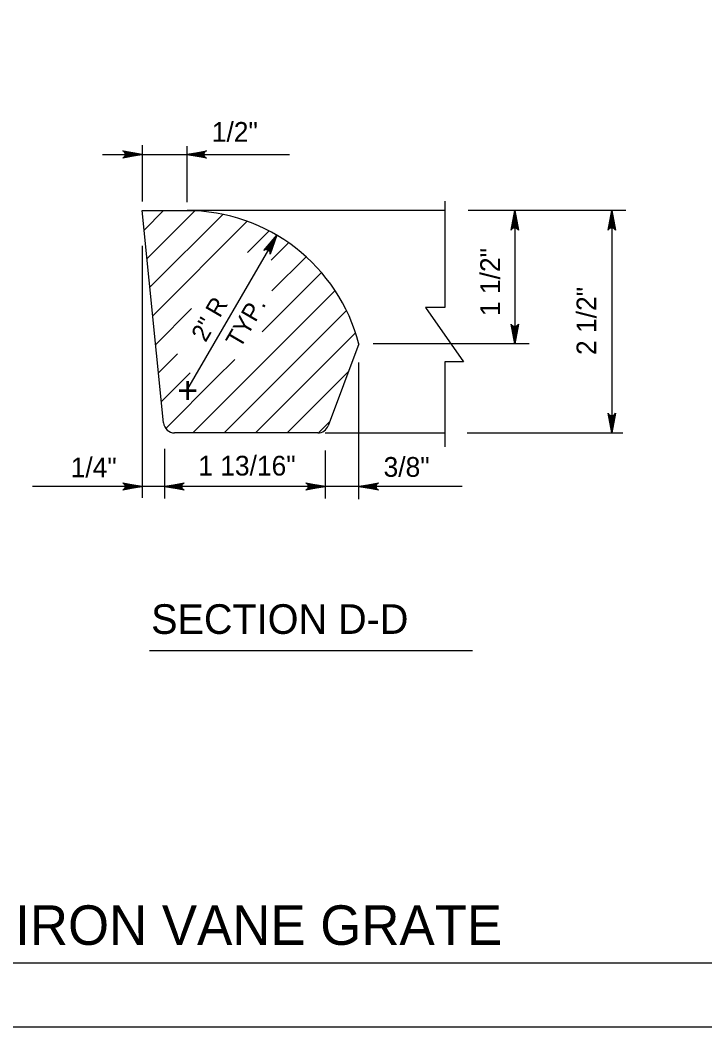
# Model space of a CAD drawing. Extents: x 2087776 to 2104538, y 970919 to 982612.
# Drawn here: x 2096713 to 2097054, y 976815 to 977317 of the extents above; entities that cross this region are included whole.
import ezdxf

# ---------------------------------------------------------------- set-up
doc = ezdxf.new("R2010")
doc.units = 0
doc.layers.add('1', color=7, linetype='Continuous')

msp = doc.modelspace()

# ---------------------------------------------------------------- linework, layer by layer
at = {"layer": '1'}
for p, q in [((2096773.77, 977254.28), (2096773.77, 977226.16)), ((2096795.92, 977253.76), (2096795.92, 977225.88)), ((2096753.92, 977249.72), (2096847.23, 977249.72)), ((2096924.63, 977226.43), (2096924.63, 977173.43)), ((2096784.34, 977115.93), (2096773.77, 977221.68)), ((2096773.77, 977221.68), (2096796.17, 977221.68)), ((2096924.63, 977221.68), (2096796.17, 977221.68)), ((2097014.91, 977221.68), (2096936.25, 977221.68)), ((2096959.46, 977221.68), (2096959.46, 977155.37)), ((2097007.85, 977221.68), (2097007.85, 977110.95)), ((2096840.9, 977209.43), (2096795.86, 977132.05)), ((2096773.77, 977204.17), (2096773.77, 977078.64)), ((2096924.63, 977173.43), (2096914.98, 977173.43)), ((2096914.98, 977173.43), (2096934, 977146.35)), ((2096881.73, 977155.37), (2096866.47, 977114.54)), ((2096966.68, 977155.37), (2096888.93, 977155.37)), ((2096881.73, 977077.85), (2096881.73, 977146.01)), ((2096934, 977146.35), (2096924.63, 977146.35)), ((2096924.63, 977146.35), (2096924.63, 977104.04)), ((2096795.86, 977132.05), (2096795.86, 977132.05)), ((2096861.28, 977110.95), (2096789.86, 977110.95)), ((2096864.95, 977110.95), (2096924.63, 977110.95)), ((2096935.77, 977110.95), (2097013.38, 977110.95)), ((2096784.84, 977103), (2096784.84, 977078.25)), ((2096865.13, 977078.25), (2096865.13, 977102.11)), ((2096933.35, 977084.24), (2096718.94, 977084.24)), ((2096777.42, 977002.5), (2096938.49, 977002.5)), ((2096478.9, 976846.96), (2097073.31, 976846.96))]:
    msp.add_line(p, q, dxfattribs=at)
for points in [[(2098759.93, 976815.01), (2098759.93, 978665.4), (2096181.19, 978665.4), (2096181.19, 976815.01), (2098759.93, 976815.01), (2098759.93, 976901.49), (2098103.76, 976901.49), (2098103.76, 977113.68), (2098759.93, 977113.68), (2098759.93, 977208.71), (2098103.76, 977208.71), (2098103.76, 976815.01), (2098362.29, 976815.01), (2098362.29, 976901.49), (2098362.29, 976815.01), (2098614.92, 976815.01), (2098614.92, 976901.49), (2098614.92, 976861.08), (2098759.93, 976861.08)], [(2096773.77, 977249.72), (2096763.99, 977247.88), (2096764.37, 977248.15), (2096764.74, 977248.41), (2096764.94, 977248.73), (2096765.13, 977249.06), (2096765.19, 977249.39), (2096765.24, 977249.72), (2096765.19, 977250.05), (2096765.13, 977250.37), (2096764.94, 977250.7), (2096764.74, 977251.03), (2096764.37, 977251.29), (2096763.99, 977251.55), (2096773.77, 977249.72), (2096764.37, 977251.29), (2096764.74, 977251.03), (2096773.77, 977249.72), (2096764.94, 977250.7), (2096765.13, 977250.37), (2096773.77, 977249.72), (2096765.19, 977250.05), (2096765.24, 977249.72), (2096773.77, 977249.72), (2096765.19, 977249.39), (2096765.13, 977249.06), (2096773.77, 977249.72), (2096764.94, 977248.73), (2096764.74, 977248.41), (2096773.77, 977249.72), (2096764.37, 977248.15)], [(2096795.92, 977249.72), (2096805.7, 977251.55), (2096805.33, 977251.29), (2096804.95, 977251.03), (2096804.76, 977250.7), (2096804.56, 977250.37), (2096804.51, 977250.05), (2096804.45, 977249.72), (2096804.51, 977249.39), (2096804.56, 977249.06), (2096804.76, 977248.73), (2096804.95, 977248.41), (2096805.33, 977248.15), (2096805.7, 977247.88), (2096795.92, 977249.72), (2096805.33, 977248.15), (2096804.95, 977248.41), (2096795.92, 977249.72), (2096804.76, 977248.73), (2096804.56, 977249.06), (2096795.92, 977249.72), (2096804.51, 977249.39), (2096804.45, 977249.72), (2096795.92, 977249.72), (2096804.51, 977250.05), (2096804.56, 977250.37), (2096795.92, 977249.72), (2096804.76, 977250.7), (2096804.95, 977251.03), (2096795.92, 977249.72), (2096805.33, 977251.29)], [(2096774.74, 977212.02), (2096784.4, 977221.68)], [(2096776.16, 977197.78), (2096799.96, 977221.58)], [(2096959.46, 977221.68), (2096961.3, 977211.9), (2096961.04, 977212.27), (2096960.78, 977212.65), (2096960.45, 977212.84), (2096960.12, 977213.04), (2096959.79, 977213.09), (2096959.46, 977213.15), (2096959.13, 977213.09), (2096958.81, 977213.04), (2096958.48, 977212.84), (2096958.15, 977212.65), (2096957.89, 977212.27), (2096957.63, 977211.9), (2096959.46, 977221.68), (2096957.89, 977212.27), (2096958.15, 977212.65), (2096959.46, 977221.68), (2096958.48, 977212.84), (2096958.81, 977213.04), (2096959.46, 977221.68), (2096959.13, 977213.09), (2096959.46, 977213.15), (2096959.46, 977221.68), (2096959.79, 977213.09), (2096960.12, 977213.04), (2096959.46, 977221.68), (2096960.45, 977212.84), (2096960.78, 977212.65), (2096959.46, 977221.68), (2096961.04, 977212.27)], [(2097007.85, 977221.68), (2097009.68, 977211.9), (2097009.42, 977212.27), (2097009.16, 977212.65), (2097008.83, 977212.84), (2097008.5, 977213.04), (2097008.18, 977213.09), (2097007.85, 977213.15), (2097007.52, 977213.09), (2097007.19, 977213.04), (2097006.86, 977212.84), (2097006.54, 977212.65), (2097006.28, 977212.27), (2097006.01, 977211.9), (2097007.85, 977221.68), (2097006.28, 977212.27), (2097006.54, 977212.65), (2097007.85, 977221.68), (2097006.86, 977212.84), (2097007.19, 977213.04), (2097007.85, 977221.68), (2097007.52, 977213.09), (2097007.85, 977213.15), (2097007.85, 977221.68), (2097008.18, 977213.09), (2097008.5, 977213.04), (2097007.85, 977221.68), (2097008.83, 977212.84), (2097009.16, 977212.65), (2097007.85, 977221.68), (2097009.42, 977212.27)], [(2096777.59, 977183.55), (2096813.88, 977219.84)], [(2096779.01, 977169.31), (2096826.09, 977216.39)], [(2096826.26, 977200.89), (2096836.97, 977211.6)], [(2096840.9, 977209.43), (2096837.56, 977200.05), (2096837.53, 977200.51), (2096837.49, 977200.97), (2096837.3, 977201.3), (2096837.12, 977201.63), (2096836.86, 977201.85), (2096836.61, 977202.06), (2096836.3, 977202.18), (2096835.98, 977202.29), (2096835.6, 977202.29), (2096835.22, 977202.29), (2096834.81, 977202.09), (2096834.39, 977201.9), (2096840.9, 977209.43), (2096834.81, 977202.09), (2096835.22, 977202.29), (2096840.9, 977209.43), (2096835.6, 977202.29), (2096835.98, 977202.29), (2096840.9, 977209.43), (2096836.3, 977202.18), (2096836.61, 977202.06), (2096840.9, 977209.43), (2096836.86, 977201.85), (2096837.12, 977201.63), (2096840.9, 977209.43), (2096837.3, 977201.3), (2096837.49, 977200.97), (2096840.9, 977209.43), (2096837.53, 977200.51)], [(2096837.95, 977196.93), (2096846.71, 977205.7)], [(2096838.4, 977181.72), (2096855.43, 977198.74)], [(2096833.58, 977161.23), (2096863.16, 977190.81)], [(2096856.84, 977168.85), (2096869.88, 977181.89)], [(2096780.43, 977155.07), (2096798.35, 977172.99)], [(2096814.61, 977110.95), (2096875.58, 977171.92)], [(2096815.47, 977127.48), (2096857.26, 977169.27)], [(2096959.46, 977155.37), (2096957.63, 977165.16), (2096957.89, 977164.78), (2096958.15, 977164.41), (2096958.48, 977164.21), (2096958.81, 977164.02), (2096959.13, 977163.96), (2096959.46, 977163.91), (2096959.79, 977163.96), (2096960.12, 977164.02), (2096960.45, 977164.21), (2096960.78, 977164.41), (2096961.04, 977164.78), (2096961.3, 977165.16), (2096959.46, 977155.37), (2096961.04, 977164.78), (2096960.78, 977164.41), (2096959.46, 977155.37), (2096960.45, 977164.21), (2096960.12, 977164.02), (2096959.46, 977155.37), (2096959.79, 977163.96), (2096959.46, 977163.91), (2096959.46, 977155.37), (2096959.13, 977163.96), (2096958.81, 977164.02), (2096959.46, 977155.37), (2096958.48, 977164.21), (2096958.15, 977164.41), (2096959.46, 977155.37), (2096957.89, 977164.78)], [(2096830.27, 977110.95), (2096880.11, 977160.79)], [(2096781.86, 977140.83), (2096791.3, 977150.28)], [(2096810.16, 977137.81), (2096819.86, 977147.51)], [(2096783.28, 977126.6), (2096797.55, 977140.87)], [(2096845.92, 977110.95), (2096876.59, 977141.61)], [(2096785.46, 977113.11), (2096810.98, 977138.64)], [(2096798.94, 977110.95), (2096815.36, 977127.36)], [(2097007.85, 977110.95), (2097006.01, 977120.73), (2097006.28, 977120.35), (2097006.54, 977119.98), (2097006.86, 977119.78), (2097007.19, 977119.59), (2097007.52, 977119.53), (2097007.85, 977119.48), (2097008.18, 977119.53), (2097008.5, 977119.59), (2097008.83, 977119.78), (2097009.16, 977119.98), (2097009.42, 977120.35), (2097009.68, 977120.73), (2097007.85, 977110.95), (2097009.42, 977120.35), (2097009.16, 977119.98), (2097007.85, 977110.95), (2097008.83, 977119.78), (2097008.5, 977119.59), (2097007.85, 977110.95), (2097008.18, 977119.53), (2097007.85, 977119.48), (2097007.85, 977110.95), (2097007.52, 977119.53), (2097007.19, 977119.59), (2097007.85, 977110.95), (2097006.86, 977119.78), (2097006.54, 977119.98), (2097007.85, 977110.95), (2097006.28, 977120.35)], [(2096861.6, 977110.96), (2096867.24, 977116.6)], [(2096773.77, 977084.24), (2096763.99, 977082.41), (2096764.37, 977082.67), (2096764.74, 977082.93), (2096764.94, 977083.26), (2096765.13, 977083.58), (2096765.19, 977083.91), (2096765.24, 977084.24), (2096765.19, 977084.57), (2096765.13, 977084.9), (2096764.94, 977085.22), (2096764.74, 977085.55), (2096764.37, 977085.81), (2096763.99, 977086.07), (2096773.77, 977084.24), (2096764.37, 977085.81), (2096764.74, 977085.55), (2096773.77, 977084.24), (2096764.94, 977085.22), (2096765.13, 977084.9), (2096773.77, 977084.24), (2096765.19, 977084.57), (2096765.24, 977084.24), (2096773.77, 977084.24), (2096765.19, 977083.91), (2096765.13, 977083.58), (2096773.77, 977084.24), (2096764.94, 977083.26), (2096764.74, 977082.93), (2096773.77, 977084.24), (2096764.37, 977082.67)], [(2096784.84, 977084.24), (2096794.63, 977086.07), (2096794.25, 977085.81), (2096793.87, 977085.55), (2096793.68, 977085.22), (2096793.49, 977084.9), (2096793.43, 977084.57), (2096793.37, 977084.24), (2096793.43, 977083.91), (2096793.49, 977083.58), (2096793.68, 977083.26), (2096793.87, 977082.93), (2096794.25, 977082.67), (2096794.63, 977082.41), (2096784.84, 977084.24), (2096794.25, 977082.67), (2096793.87, 977082.93), (2096784.84, 977084.24), (2096793.68, 977083.26), (2096793.49, 977083.58), (2096784.84, 977084.24), (2096793.43, 977083.91), (2096793.37, 977084.24), (2096784.84, 977084.24), (2096793.43, 977084.57), (2096793.49, 977084.9), (2096784.84, 977084.24), (2096793.68, 977085.22), (2096793.87, 977085.55), (2096784.84, 977084.24), (2096794.25, 977085.81)], [(2096865.13, 977084.24), (2096855.34, 977082.41), (2096855.72, 977082.67), (2096856.09, 977082.93), (2096856.29, 977083.26), (2096856.48, 977083.58), (2096856.54, 977083.91), (2096856.6, 977084.24), (2096856.54, 977084.57), (2096856.48, 977084.9), (2096856.29, 977085.22), (2096856.09, 977085.55), (2096855.72, 977085.81), (2096855.34, 977086.07), (2096865.13, 977084.24), (2096855.72, 977085.81), (2096856.09, 977085.55), (2096865.13, 977084.24), (2096856.29, 977085.22), (2096856.48, 977084.9), (2096865.13, 977084.24), (2096856.54, 977084.57), (2096856.6, 977084.24), (2096865.13, 977084.24), (2096856.54, 977083.91), (2096856.48, 977083.58), (2096865.13, 977084.24), (2096856.29, 977083.26), (2096856.09, 977082.93), (2096865.13, 977084.24), (2096855.72, 977082.67)], [(2096881.73, 977084.24), (2096891.52, 977086.07), (2096891.14, 977085.81), (2096890.76, 977085.55), (2096890.57, 977085.22), (2096890.38, 977084.9), (2096890.32, 977084.57), (2096890.26, 977084.24), (2096890.32, 977083.91), (2096890.38, 977083.58), (2096890.57, 977083.26), (2096890.76, 977082.93), (2096891.14, 977082.67), (2096891.52, 977082.41), (2096881.73, 977084.24), (2096891.14, 977082.67), (2096890.76, 977082.93), (2096881.73, 977084.24), (2096890.57, 977083.26), (2096890.38, 977083.58), (2096881.73, 977084.24), (2096890.32, 977083.91), (2096890.26, 977084.24), (2096881.73, 977084.24), (2096890.32, 977084.57), (2096890.38, 977084.9), (2096881.73, 977084.24), (2096890.57, 977085.22), (2096890.76, 977085.55), (2096881.73, 977084.24), (2096891.14, 977085.81)]]:
    msp.add_lwpolyline(points, dxfattribs=at)
for centre, radius, start, end in [((2096795.97, 977133.09), 88.58, 14.3767, 90.1346), ((2096789.86, 977116.48), 5.54, 185.7106, 270), ((2096861.28, 977116.48), 5.54, 270, 339.5022)]:
    msp.add_arc(centre, radius, start, end, dxfattribs=at)

# ---------------------------------------------------------------- texts
for s, height, p in [('1/2"', 9.843, (2096808.41, 977255.99)), ('+', 13.29, (2096791.21, 977125.62)), ('1 13/16"', 9.843, (2096801.64, 977089.7)), ('1/4"', 9.843, (2096738.02, 977088.83)), ('3/8"', 9.843, (2096894.08, 977089.07)), ('SECTION D-D', 14.7633, (2096778.16, 977010.81)), ('ONE PIECE CAST IRON VANE GRATE', 19.685, (2096482.21, 976855.86))]:
    msp.add_text(s, height=height, dxfattribs=at).set_placement(p)
for s, height, rotation, p in [('1 1/2"', 9.843, 90, (2096952.13, 977169.13)), ('2 1/2"', 9.843, 90, (2097000.16, 977149.75)), ('2" R', 8.858, 59.798, (2096805.31, 977155.68)), ('TYP.', 8.858, 59.798, (2096822.53, 977152.58))]:
    msp.add_text(s, height=height, rotation=rotation, dxfattribs=at).set_placement(p)

doc.saveas('drawing.dxf')
